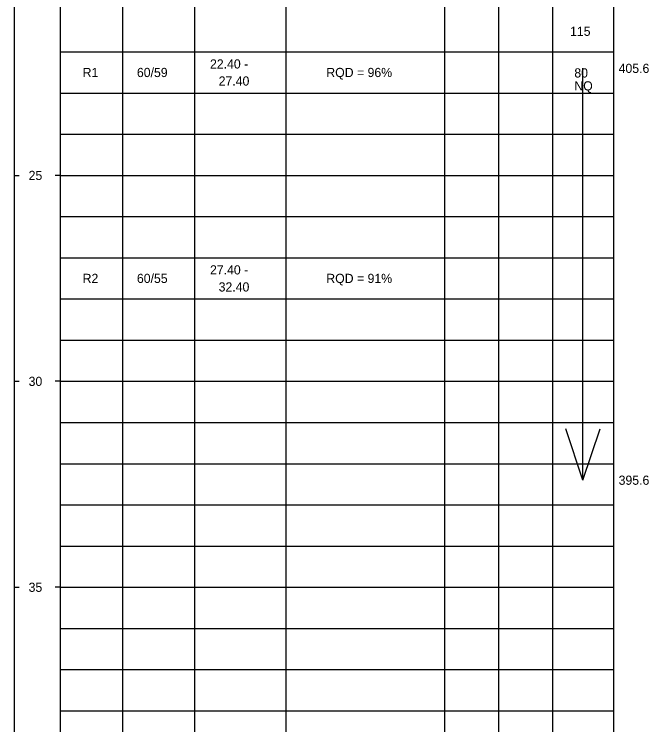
# Model space of a CAD drawing. Extents: x 9419 to 9552, y 6780 to 6865.
# Drawn here: x 9460.28 to 9475.7, y 6808.67 to 6825.93 of the extents above; entities that cross this region are included whole.
import ezdxf

# ---------------------------------------------------------------- set-up
doc = ezdxf.new("R2010")
doc.units = 0
doc.layers.add('7', color=7, linetype='Continuous')

msp = doc.modelspace()

# ---------------------------------------------------------------- linework, layer by layer
at = {"layer": '7'}
for p, q in [((9474.097, 6822.011), (9474.097, 6824.611)), ((9474.097, 6814.611), (9474.097, 6822.011)), ((9474.097, 6814.611), (9473.68, 6815.861)), ((9474.097, 6814.611), (9474.514, 6815.861))]:
    msp.add_line(p, q, dxfattribs=at)
for points in [[(9460.282, 6860.114), (9460.282, 6821.983)], [(9461.4, 6850.528), (9461.4, 6821.983)], [(9462.909, 6849.992), (9462.909, 6821.983)], [(9464.665, 6849.992), (9464.665, 6821.983)], [(9466.879, 6849.992), (9466.879, 6821.983)], [(9470.734, 6849.992), (9470.734, 6821.983)], [(9472.046, 6849.992), (9472.046, 6821.983)], [(9473.359, 6849.992), (9473.359, 6821.983)], [(9474.835, 6849.992), (9474.835, 6821.983)], [(9461.4, 6825.011), (9462.909, 6825.011)], [(9462.909, 6825.011), (9464.665, 6825.011)], [(9464.665, 6825.011), (9466.879, 6825.011)], [(9466.879, 6825.011), (9470.734, 6825.011)], [(9470.734, 6825.011), (9472.046, 6825.011)], [(9472.046, 6825.011), (9473.359, 6825.011)], [(9473.359, 6825.011), (9474.835, 6825.011)], [(9461.4, 6824.011), (9462.909, 6824.011)], [(9462.909, 6824.011), (9464.665, 6824.011)], [(9464.665, 6824.011), (9466.879, 6824.011)], [(9466.879, 6824.011), (9470.734, 6824.011)], [(9470.734, 6824.011), (9472.046, 6824.011)], [(9472.046, 6824.011), (9473.359, 6824.011)], [(9473.359, 6824.011), (9474.835, 6824.011)], [(9461.4, 6823.011), (9462.909, 6823.011)], [(9462.909, 6823.011), (9464.665, 6823.011)], [(9464.665, 6823.011), (9466.879, 6823.011)], [(9466.879, 6823.011), (9470.734, 6823.011)], [(9470.734, 6823.011), (9472.046, 6823.011)], [(9472.046, 6823.011), (9473.359, 6823.011)], [(9473.359, 6823.011), (9474.835, 6823.011)], [(9460.282, 6822.038), (9460.282, 6791.992)], [(9460.282, 6822.011), (9460.404, 6822.011)], [(9461.4, 6822.011), (9461.279, 6822.011)], [(9461.4, 6822.038), (9461.4, 6796.983)], [(9461.4, 6822.011), (9462.909, 6822.011)], [(9462.909, 6822.038), (9462.909, 6796.983)], [(9462.909, 6822.011), (9464.665, 6822.011)], [(9464.665, 6822.038), (9464.665, 6796.983)], [(9464.665, 6822.011), (9466.879, 6822.011)], [(9466.879, 6822.038), (9466.879, 6796.983)], [(9466.879, 6822.011), (9470.734, 6822.011)], [(9470.734, 6822.038), (9470.734, 6796.983)], [(9470.734, 6822.011), (9472.046, 6822.011)], [(9472.046, 6822.038), (9472.046, 6796.983)], [(9472.046, 6822.011), (9473.359, 6822.011)], [(9473.359, 6822.038), (9473.359, 6796.983)], [(9473.359, 6822.011), (9474.835, 6822.011)], [(9474.835, 6822.038), (9474.835, 6796.983)], [(9461.4, 6821.011), (9462.909, 6821.011)], [(9462.909, 6821.011), (9464.665, 6821.011)], [(9464.665, 6821.011), (9466.879, 6821.011)], [(9466.879, 6821.011), (9470.734, 6821.011)], [(9470.734, 6821.011), (9472.046, 6821.011)], [(9472.046, 6821.011), (9473.359, 6821.011)], [(9473.359, 6821.011), (9474.835, 6821.011)], [(9461.4, 6820.011), (9462.909, 6820.011)], [(9462.909, 6820.011), (9464.665, 6820.011)], [(9464.665, 6820.011), (9466.879, 6820.011)], [(9466.879, 6820.011), (9470.734, 6820.011)], [(9470.734, 6820.011), (9472.046, 6820.011)], [(9472.046, 6820.011), (9473.359, 6820.011)], [(9473.359, 6820.011), (9474.835, 6820.011)], [(9461.4, 6819.011), (9462.909, 6819.011)], [(9462.909, 6819.011), (9464.665, 6819.011)], [(9464.665, 6819.011), (9466.879, 6819.011)], [(9466.879, 6819.011), (9470.734, 6819.011)], [(9470.734, 6819.011), (9472.046, 6819.011)], [(9472.046, 6819.011), (9473.359, 6819.011)], [(9473.359, 6819.011), (9474.835, 6819.011)], [(9461.4, 6818.011), (9462.909, 6818.011)], [(9462.909, 6818.011), (9464.665, 6818.011)], [(9464.665, 6818.011), (9466.879, 6818.011)], [(9466.879, 6818.011), (9470.734, 6818.011)], [(9470.734, 6818.011), (9472.046, 6818.011)], [(9472.046, 6818.011), (9473.359, 6818.011)], [(9473.359, 6818.011), (9474.835, 6818.011)], [(9460.282, 6817.011), (9460.404, 6817.011)], [(9461.4, 6817.011), (9461.279, 6817.011)], [(9461.4, 6817.011), (9462.909, 6817.011)], [(9462.909, 6817.011), (9464.665, 6817.011)], [(9464.665, 6817.011), (9466.879, 6817.011)], [(9466.879, 6817.011), (9470.734, 6817.011)], [(9470.734, 6817.011), (9472.046, 6817.011)], [(9472.046, 6817.011), (9473.359, 6817.011)], [(9473.359, 6817.011), (9474.835, 6817.011)], [(9461.4, 6816.011), (9462.909, 6816.011)], [(9462.909, 6816.011), (9464.665, 6816.011)], [(9464.665, 6816.011), (9466.879, 6816.011)], [(9466.879, 6816.011), (9470.734, 6816.011)], [(9470.734, 6816.011), (9472.046, 6816.011)], [(9472.046, 6816.011), (9473.359, 6816.011)], [(9473.359, 6816.011), (9474.835, 6816.011)], [(9461.4, 6815.011), (9462.909, 6815.011)], [(9462.909, 6815.011), (9464.665, 6815.011)], [(9464.665, 6815.011), (9466.879, 6815.011)], [(9466.879, 6815.011), (9470.734, 6815.011)], [(9470.734, 6815.011), (9472.046, 6815.011)], [(9472.046, 6815.011), (9473.359, 6815.011)], [(9473.359, 6815.011), (9474.835, 6815.011)], [(9461.4, 6814.011), (9462.909, 6814.011)], [(9462.909, 6814.011), (9464.665, 6814.011)], [(9464.665, 6814.011), (9466.879, 6814.011)], [(9466.879, 6814.011), (9470.734, 6814.011)], [(9470.734, 6814.011), (9472.046, 6814.011)], [(9472.046, 6814.011), (9473.359, 6814.011)], [(9473.359, 6814.011), (9474.835, 6814.011)], [(9461.4, 6813.011), (9462.909, 6813.011)], [(9462.909, 6813.011), (9464.665, 6813.011)], [(9464.665, 6813.011), (9466.879, 6813.011)], [(9466.879, 6813.011), (9470.734, 6813.011)], [(9470.734, 6813.011), (9472.046, 6813.011)], [(9472.046, 6813.011), (9473.359, 6813.011)], [(9473.359, 6813.011), (9474.835, 6813.011)], [(9460.282, 6812.011), (9460.404, 6812.011)], [(9461.4, 6812.011), (9461.279, 6812.011)], [(9461.4, 6812.011), (9462.909, 6812.011)], [(9462.909, 6812.011), (9464.665, 6812.011)], [(9464.665, 6812.011), (9466.879, 6812.011)], [(9466.879, 6812.011), (9470.734, 6812.011)], [(9470.734, 6812.011), (9472.046, 6812.011)], [(9472.046, 6812.011), (9473.359, 6812.011)], [(9473.359, 6812.011), (9474.835, 6812.011)], [(9461.4, 6811.011), (9462.909, 6811.011)], [(9462.909, 6811.011), (9464.665, 6811.011)], [(9464.665, 6811.011), (9466.879, 6811.011)], [(9466.879, 6811.011), (9470.734, 6811.011)], [(9470.734, 6811.011), (9472.046, 6811.011)], [(9472.046, 6811.011), (9473.359, 6811.011)], [(9473.359, 6811.011), (9474.835, 6811.011)], [(9461.4, 6810.011), (9462.909, 6810.011)], [(9462.909, 6810.011), (9464.665, 6810.011)], [(9464.665, 6810.011), (9466.879, 6810.011)], [(9466.879, 6810.011), (9470.734, 6810.011)], [(9470.734, 6810.011), (9472.046, 6810.011)], [(9472.046, 6810.011), (9473.359, 6810.011)], [(9473.359, 6810.011), (9474.835, 6810.011)], [(9461.4, 6809.011), (9462.909, 6809.011)], [(9462.909, 6809.011), (9464.665, 6809.011)], [(9464.665, 6809.011), (9466.879, 6809.011)], [(9466.879, 6809.011), (9470.734, 6809.011)], [(9470.734, 6809.011), (9472.046, 6809.011)], [(9472.046, 6809.011), (9473.359, 6809.011)], [(9473.359, 6809.011), (9474.835, 6809.011)]]:
    msp.add_lwpolyline(points, dxfattribs=at)

# ---------------------------------------------------------------- texts
for s, p in [('115', (9473.783, 6825.399)), ('22.40 -', (9465.038, 6824.606)), ('R1', (9461.945, 6824.399)), ('60/59', (9463.263, 6824.399)), ('RQD = 96%%%', (9467.863, 6824.399)), ('80', (9473.887, 6824.388)), ('405.6', (9474.963, 6824.499)), ('27.40', (9465.248, 6824.192)), ('NQ', (9473.887, 6824.074)), ('25', (9460.632, 6821.899)), ('27.40 -', (9465.038, 6819.606)), ('R2', (9461.945, 6819.399)), ('60/55', (9463.263, 6819.399)), ('RQD = 91%%%', (9467.863, 6819.399)), ('32.40', (9465.248, 6819.192)), ('30', (9460.632, 6816.899)), ('395.6', (9474.963, 6814.499)), ('35', (9460.632, 6811.899))]:
    msp.add_text(s, height=0.2228, dxfattribs=at).set_placement(p)

doc.saveas('drawing.dxf')
